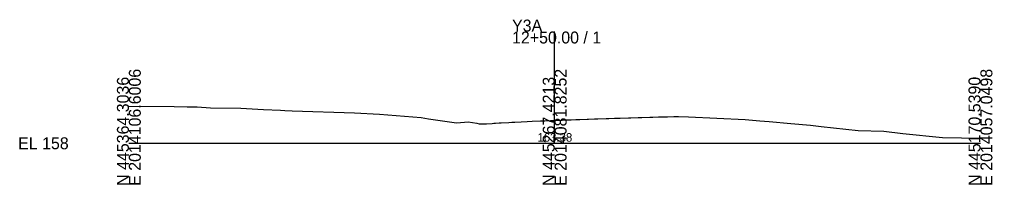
# Model space of a CAD drawing. Extents: x -26 to 205, y -10 to 5029.
# Drawn here: x -25.7 to 202.8, y 4990.3 to 5029.1 of the extents above; entities that cross this region are included whole.
import ezdxf

# ---------------------------------------------------------------- set-up
doc = ezdxf.new("R2010")
doc.units = 0
for name, color, linetype in [('Default', 7, 'Continuous'), ('Exist Cross Section Cell', 7, 'Continuous'), ('Exist XS Center Line Elevation Label', 7, 'Continuous'), ('Exist XS Ground Line', 7, 'Continuous')]:
    doc.layers.add(name, color=color, linetype=linetype)

msp = doc.modelspace()

# ---------------------------------------------------------------- linework, layer by layer
at = {"layer": 'Exist Cross Section Cell'}
for p, q in [((100, 5000), (100, 5026.24)), ((0, 5000), (100, 5000)), ((100, 5000), (200, 5000))]:
    msp.add_line(p, q, dxfattribs=at)
at = {"layer": 'Exist XS Ground Line'}
msp.add_lwpolyline([(0, 5008.75), (10.64, 5008.62), (13.72, 5008.59), (16.01, 5008.53), (19.19, 5008.35), (26.33, 5008.22), (31.64, 5007.96), (35.63, 5007.77), (36.66, 5007.71), (38.38, 5007.63), (52.98, 5007.11), (58.9, 5006.8), (68.68, 5006.04), (70.4, 5005.76), (76.94, 5004.82), (78.82, 5004.93), (79.68, 5005), (81.75, 5004.71), (82.28, 5004.55), (83.99, 5004.54), (85.32, 5004.64), (85.74, 5004.7), (86.13, 5004.74), (86.93, 5004.78), (87.43, 5004.81), (89.24, 5004.91), (89.94, 5004.95), (90.68, 5004.98), (92.12, 5005.04), (93.58, 5005.11), (94.71, 5005.16), (96.66, 5005.26), (97.28, 5005.28), (97.67, 5005.3), (99.06, 5005.35), (100, 5005.38), (101.78, 5005.44), (102.43, 5005.47), (103.85, 5005.52), (105, 5005.56), (105.88, 5005.6), (107.63, 5005.66), (107.96, 5005.67), (109.37, 5005.73), (110.13, 5005.76), (112.08, 5005.81), (112.73, 5005.84), (114.09, 5005.89), (115.35, 5005.92), (117.31, 5005.99), (117.88, 5006.01), (119.6, 5006.06), (120.45, 5006.08), (122.32, 5006.13), (123.07, 5006.14), (124.39, 5006.18), (125.66, 5006.22), (126.51, 5006.24), (128, 5006.29), (128.76, 5006.3), (129.11, 5006.31), (131.4, 5006.18), (144.76, 5005.56), (148.22, 5005.29), (150.37, 5005.13), (155.46, 5004.68), (160.06, 5004.29), (162.56, 5003.96), (171.3, 5002.96), (177.28, 5002.88), (181.77, 5002.3), (191.11, 5001.36), (200, 5001.17)], dxfattribs=at)

# ---------------------------------------------------------------- texts
at = {"layer": 'Default'}
msp.add_text('-', height=0.0001, dxfattribs=at).set_placement((0, 5000))
at = {"layer": 'Exist Cross Section Cell'}
for s, p in [('Y3A', (90, 5026.24)), ('12+50.00 / 1', (90, 5023.44)), ('EL 158', (-26, 4998.6))]:
    msp.add_text(s, height=2.8, dxfattribs=at).set_placement(p)
for s, p in [('E 2014106.6006', (2.8, 4990)), ('E 2014081.8252', (102.8, 4990)), ('E 2014057.0498', (202.8, 4990)), ('N 445364.3036', (0, 4990)), ('N 445267.4213', (100, 4990)), ('N 445170.5390', (200, 4990))]:
    msp.add_text(s, height=2.8, rotation=90, dxfattribs=at).set_placement(p)
at = {"layer": 'Exist XS Center Line Elevation Label'}
msp.add_text('163.38', height=2, dxfattribs=at).set_placement((95.96, 5000.38))

doc.saveas('drawing.dxf')
